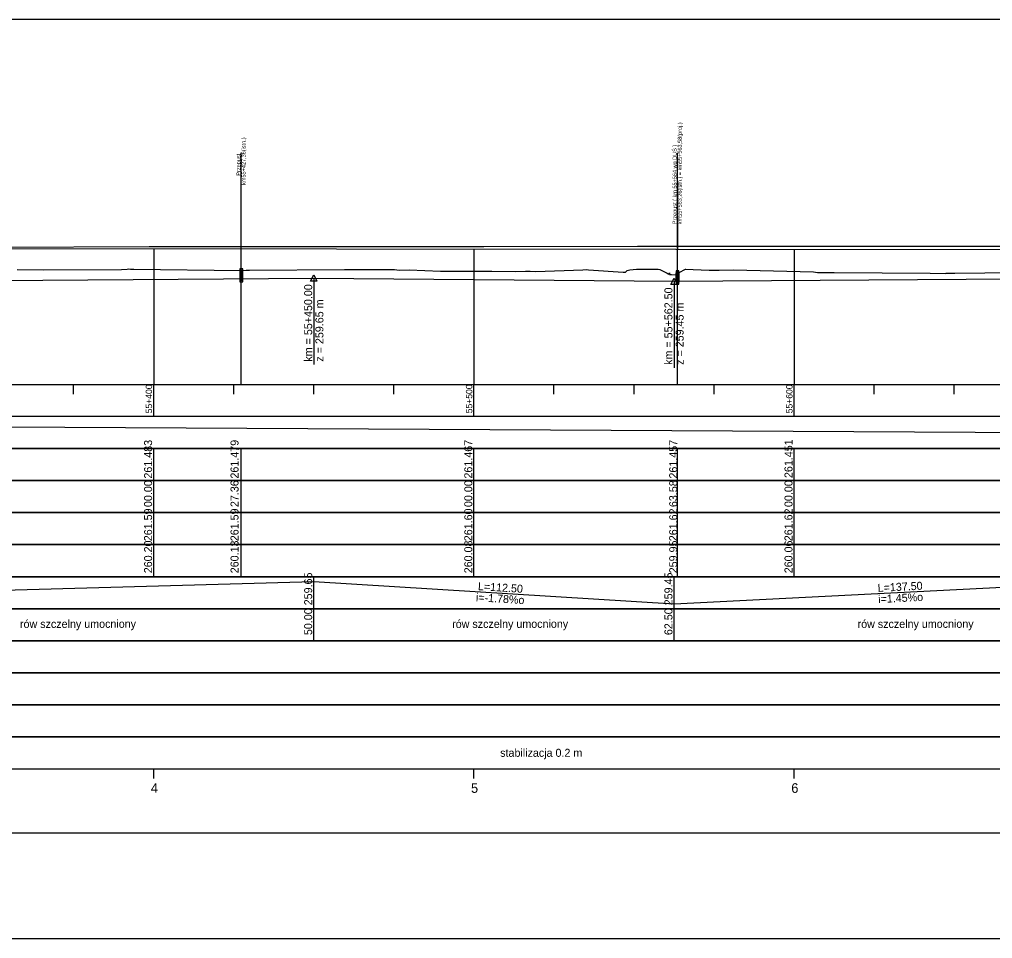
# Model space of a CAD drawing. Extents: x 6445630 to 6518227, y 5499240 to 5511716.
# Drawn here: x 6454589.3 to 6454893.2, y 5508418.3 to 5508705.3 of the extents above; entities that cross this region are included whole.
import ezdxf

# ---------------------------------------------------------------- set-up
doc = ezdxf.new("R2010")
doc.units = 0
for name, color, linetype in [('TOR_PROF-obiekty+opisy', 7, 'Continuous'), ('TOR_PROF-opisy pomocnicze', 7, 'Continuous'), ('TOR_PROF-rowy otwarte', 7, 'Continuous'), ('TOR_PROF-tabelka-geometria T1', 7, 'Continuous'), ('TOR_PROF-tabelka-kilometracja', 7, 'Continuous'), ('TOR_PROF-tabelka-odleglosci T1', 7, 'Continuous'), ('TOR_PROF-tabelka-pochylenia proj T1', 7, 'Continuous'), ('TOR_PROF-tabelka-rodzaj rowu T1', 7, 'Continuous'), ('TOR_PROF-tabelka-rowyT1', 7, 'Continuous'), ('TOR_PROF-tabelka-rurociagi T1', 7, 'Continuous'), ('TOR_PROF-tabelka-rzedne istn T1', 7, 'Continuous'), ('TOR_PROF-tabelka-rzedne proj T1', 7, 'Continuous'), ('TOR_PROF-tabelka-teren istniejacy T1', 7, 'Continuous'), ('TOR_PROF-tabelka-warstwa ochronna T1', 7, 'Continuous'), ('TOR_PROF-tor istniejacy T2', 7, 'Continuous'), ('TOR_PROF-tor projektowany', 7, 'Continuous'), ('TOR_PROF-uklad odniesienia', 7, 'Continuous'), ('TOR_PROF-warstwa ochronna', 7, 'Continuous'), ('TOR_RAMKI-dodatkowe3', 7, 'Continuous'), ('TOR_RAMKI-MASKA WYCIECIA', 7, 'Continuous')]:
    doc.layers.add(name, color=color, linetype=linetype)

msp = doc.modelspace()

# ---------------------------------------------------------------- linework, layer by layer
at = {"layer": 'TOR_PROF-obiekty+opisy'}
for p, q in [((6454658.57, 5508591.29), (6454658.57, 5508663.68)), ((6454794.79, 5508591.29), (6454794.79, 5508663.58)), ((6454794.79, 5508654.58), (6454794.79, 5508633.58)), ((6454794.79, 5508654.58), (6454794.79, 5508633.58))]:
    msp.add_line(p, q, dxfattribs=at)
for points in [[(6454659.03, 5508627.39), (6454658.11, 5508627.39), (6454658.11, 5508623.31), (6454659.03, 5508623.31)], [(6454658.95, 5508626.85), (6454658.2, 5508626.85), (6454658.2, 5508623.85), (6454658.95, 5508623.85)], [(6454795.25, 5508626.76), (6454794.33, 5508626.76), (6454794.33, 5508622.68), (6454795.25, 5508622.68)], [(6454795.17, 5508626.22), (6454794.42, 5508626.22), (6454794.42, 5508623.22), (6454795.17, 5508623.22)]]:
    msp.add_lwpolyline(points, close=True, dxfattribs=at)
for points in [[(6454659.03, 5508623.31), (6454659.03, 5508627.39), (6454658.11, 5508627.39), (6454658.11, 5508623.31), (6454659.03, 5508623.31)], [(6454658.95, 5508623.85), (6454658.2, 5508623.85), (6454658.2, 5508626.85), (6454658.95, 5508626.85), (6454658.95, 5508623.85)], [(6454795.25, 5508622.68), (6454795.25, 5508626.76), (6454794.33, 5508626.76), (6454794.33, 5508622.68), (6454795.25, 5508622.68)], [(6454795.17, 5508623.22), (6454794.42, 5508623.22), (6454794.42, 5508626.22), (6454795.17, 5508626.22), (6454795.17, 5508623.22)]]:
    msp.add_lwpolyline(points, dxfattribs=at)
at = {"layer": 'TOR_PROF-opisy pomocnicze'}
for p, q in [((6454681.21, 5508624.54), (6454681.21, 5508597.54)), ((6454793.71, 5508623.54), (6454793.71, 5508596.54))]:
    msp.add_line(p, q, dxfattribs=at)
for points in [[(6454681.21, 5508625.54), (6454682.21, 5508623.54), (6454680.21, 5508623.54)], [(6454793.71, 5508624.54), (6454794.71, 5508622.54), (6454792.71, 5508622.54)]]:
    msp.add_lwpolyline(points, close=True, dxfattribs=at)
at = {"layer": 'TOR_PROF-rowy otwarte'}
for p, q in [((6454431.21, 5508622.54), (6454681.21, 5508624.54)), ((6454681.21, 5508624.54), (6454793.71, 5508623.54)), ((6454793.71, 5508623.54), (6454931.21, 5508624.54))]:
    msp.add_line(p, q, dxfattribs=at)
at = {"layer": 'TOR_PROF-tabelka-geometria T1'}
for points in [[(6452331.21, 5508451.29), (6453331.21, 5508451.29), (6453331.21, 5508448.62), (6453416.22, 5508448.62), (6453416.22, 5508451.29), (6453496.22, 5508451.29), (6453496.22, 5508453.96), (6453581.21, 5508453.96), (6453581.21, 5508451.29), (6457347.56, 5508451.29), (6457347.56, 5508448.62), (6457429.11, 5508448.62), (6457429.11, 5508451.29), (6457509.11, 5508451.29), (6457509.11, 5508453.96), (6457590.67, 5508453.96), (6457590.67, 5508451.29), (6459780.93, 5508451.29)], [(6452331.21, 5508451.29), (6462731.21, 5508451.29)]]:
    msp.add_lwpolyline(points, dxfattribs=at)
at = {"layer": 'TOR_PROF-tabelka-kilometracja'}
for points in [[(6454631.21, 5508468.29), (6454631.21, 5508471.29)], [(6454731.21, 5508468.29), (6454731.21, 5508471.29)], [(6454831.21, 5508468.29), (6454831.21, 5508471.29)]]:
    msp.add_lwpolyline(points, dxfattribs=at)
at = {"layer": 'TOR_PROF-tabelka-odleglosci T1'}
msp.add_lwpolyline([(6452331.21, 5508551.29), (6462731.21, 5508551.29), (6462731.21, 5508561.29), (6452331.21, 5508561.29)], close=True, dxfattribs=at)
for points in [[(6454631.21, 5508551.29), (6454631.21, 5508561.29)], [(6454658.57, 5508551.29), (6454658.57, 5508561.29)], [(6454731.21, 5508551.29), (6454731.21, 5508561.29)], [(6454794.79, 5508551.29), (6454794.79, 5508561.29)], [(6454831.21, 5508551.29), (6454831.21, 5508561.29)]]:
    msp.add_lwpolyline(points, dxfattribs=at)
at = {"layer": 'TOR_PROF-tabelka-pochylenia proj T1'}
msp.add_lwpolyline([(6452331.21, 5508571.29), (6462731.21, 5508571.29), (6462731.21, 5508581.29), (6452331.21, 5508581.29)], close=True, dxfattribs=at)
msp.add_lwpolyline([(6454281.21, 5508579.79), (6455551.21, 5508572.79)], dxfattribs=at)
at = {"layer": 'TOR_PROF-tabelka-rodzaj rowu T1'}
for points in [[(6452331.21, 5508511.29), (6462731.21, 5508511.29), (6462731.21, 5508521.29), (6452331.21, 5508521.29)], [(6452331.21, 5508511.29), (6462731.21, 5508511.29), (6462731.21, 5508521.29), (6452331.21, 5508521.29)], [(6452331.21, 5508491.29), (6462731.21, 5508491.29), (6462731.21, 5508501.29), (6452331.21, 5508501.29)]]:
    msp.add_lwpolyline(points, close=True, dxfattribs=at)
for points in [[(6454681.21, 5508511.29), (6454681.21, 5508521.29)], [(6454793.71, 5508511.29), (6454793.71, 5508521.29)]]:
    msp.add_lwpolyline(points, dxfattribs=at)
at = {"layer": 'TOR_PROF-tabelka-rowyT1'}
msp.add_lwpolyline([(6452331.21, 5508521.29), (6462731.21, 5508521.29), (6462731.21, 5508531.29), (6452331.21, 5508531.29)], close=True, dxfattribs=at)
msp.add_lwpolyline([(6452331.21, 5508521.29), (6462731.21, 5508521.29), (6462731.21, 5508531.29), (6452331.21, 5508531.29)], close=True, dxfattribs=at)
msp.add_lwpolyline([(6452331.21, 5508521.29), (6462731.21, 5508521.29), (6462731.21, 5508531.29), (6452331.21, 5508531.29)], close=True, dxfattribs=at)
for points in [[(6454431.21, 5508522.79), (6454681.21, 5508529.79)], [(6454681.21, 5508521.29), (6454681.21, 5508531.29)], [(6454681.21, 5508529.79), (6454793.71, 5508522.79)], [(6454793.71, 5508521.29), (6454793.71, 5508531.29)], [(6454793.71, 5508522.79), (6454931.21, 5508529.79)]]:
    msp.add_lwpolyline(points, dxfattribs=at)
at = {"layer": 'TOR_PROF-tabelka-rurociagi T1'}
msp.add_lwpolyline([(6452331.21, 5508501.29), (6462731.21, 5508501.29), (6462731.21, 5508511.29), (6452331.21, 5508511.29)], close=True, dxfattribs=at)
at = {"layer": 'TOR_PROF-tabelka-rzedne istn T1'}
msp.add_lwpolyline([(6452331.21, 5508541.29), (6462731.21, 5508541.29), (6462731.21, 5508551.29), (6452331.21, 5508551.29)], close=True, dxfattribs=at)
for points in [[(6454631.21, 5508541.29), (6454631.21, 5508551.29)], [(6454658.57, 5508541.29), (6454658.57, 5508551.29)], [(6454731.21, 5508541.29), (6454731.21, 5508551.29)], [(6454794.79, 5508541.29), (6454794.79, 5508551.29)], [(6454831.21, 5508541.29), (6454831.21, 5508551.29)], [(6454631.21, 5508531.29), (6454631.21, 5508541.29)], [(6454631.21, 5508531.29), (6454631.21, 5508541.29)], [(6454631.21, 5508531.29), (6454631.21, 5508541.29)], [(6454631.21, 5508531.29), (6454631.21, 5508541.29)], [(6454658.57, 5508531.29), (6454658.57, 5508541.29)], [(6454731.21, 5508531.29), (6454731.21, 5508541.29)], [(6454731.21, 5508531.29), (6454731.21, 5508541.29)], [(6454731.21, 5508531.29), (6454731.21, 5508541.29)], [(6454731.21, 5508531.29), (6454731.21, 5508541.29)], [(6454794.79, 5508531.29), (6454794.79, 5508541.29)], [(6454831.21, 5508531.29), (6454831.21, 5508541.29)], [(6454831.21, 5508531.29), (6454831.21, 5508541.29)], [(6454831.21, 5508531.29), (6454831.21, 5508541.29)], [(6454831.21, 5508531.29), (6454831.21, 5508541.29)]]:
    msp.add_lwpolyline(points, dxfattribs=at)
at = {"layer": 'TOR_PROF-tabelka-rzedne proj T1'}
msp.add_lwpolyline([(6452331.21, 5508561.29), (6462731.21, 5508561.29), (6462731.21, 5508571.29), (6452331.21, 5508571.29)], close=True, dxfattribs=at)
for points in [[(6454631.21, 5508561.29), (6454631.21, 5508571.29)], [(6454658.57, 5508561.29), (6454658.57, 5508571.29)], [(6454731.21, 5508561.29), (6454731.21, 5508571.29)], [(6454794.79, 5508561.29), (6454794.79, 5508571.29)], [(6454831.21, 5508561.29), (6454831.21, 5508571.29)]]:
    msp.add_lwpolyline(points, dxfattribs=at)
at = {"layer": 'TOR_PROF-tabelka-teren istniejacy T1'}
msp.add_lwpolyline([(6452331.21, 5508531.29), (6462731.21, 5508531.29), (6462731.21, 5508541.29), (6452331.21, 5508541.29)], close=True, dxfattribs=at)
msp.add_lwpolyline([(6452331.21, 5508531.29), (6462731.21, 5508531.29), (6462731.21, 5508541.29), (6452331.21, 5508541.29)], close=True, dxfattribs=at)
msp.add_lwpolyline([(6452331.21, 5508531.29), (6462731.21, 5508531.29), (6462731.21, 5508541.29), (6452331.21, 5508541.29)], close=True, dxfattribs=at)
msp.add_lwpolyline([(6452331.21, 5508531.29), (6462731.21, 5508531.29), (6462731.21, 5508541.29), (6452331.21, 5508541.29)], close=True, dxfattribs=at)
at = {"layer": 'TOR_PROF-tabelka-warstwa ochronna T1'}
msp.add_lwpolyline([(6452331.21, 5508481.29), (6462731.21, 5508481.29), (6462731.21, 5508491.29), (6452331.21, 5508491.29)], close=True, dxfattribs=at)
at = {"layer": 'TOR_PROF-tor istniejacy T2'}
msp.add_lwpolyline([(6455230.6, 5508634.64), (6455180.37, 5508634.54), (6455131.29, 5508634.54), (6455081.1, 5508634.59), (6455031.43, 5508634.54), (6454982.33, 5508634.44), (6454932.17, 5508634.44), (6454881.46, 5508634.44), (6454831.03, 5508634.39), (6454782.28, 5508634.39), (6454734.31, 5508634.29), (6454682.33, 5508634.24), (6454629.77, 5508634.24), (6454582.54, 5508634.09)], dxfattribs=at)
at = {"layer": 'TOR_PROF-tor projektowany'}
msp.add_line((6454281.21, 5508633.98), (6455551.21, 5508632.98), dxfattribs=at)
msp.add_line((6454281.21, 5508633.98), (6455551.21, 5508632.98), dxfattribs=at)
for points in [[(6454631.21, 5508633.7), (6454631.21, 5508596.29), (6454631.21, 5508591.29), (6454631.21, 5508591.29)], [(6454631.21, 5508633.7), (6454631.21, 5508596.29), (6454631.21, 5508591.29), (6454631.21, 5508591.29)], [(6454731.21, 5508633.63), (6454731.21, 5508596.29), (6454731.21, 5508591.29), (6454731.21, 5508591.29)], [(6454731.21, 5508633.63), (6454731.21, 5508596.29), (6454731.21, 5508591.29), (6454731.21, 5508591.29)], [(6454831.21, 5508633.55), (6454831.21, 5508596.29), (6454831.21, 5508591.29), (6454831.21, 5508591.29)], [(6454831.21, 5508633.55), (6454831.21, 5508596.29), (6454831.21, 5508591.29), (6454831.21, 5508591.29)]]:
    msp.add_lwpolyline(points, dxfattribs=at)
at = {"layer": 'TOR_PROF-uklad odniesienia'}
for p, q in [((6452331.21, 5508591.29), (6462731.21, 5508591.29)), ((6452331.21, 5508591.29), (6462731.21, 5508591.29)), ((6454606.21, 5508588.29), (6454606.21, 5508591.29)), ((6454606.21, 5508588.29), (6454606.21, 5508591.29)), ((6454631.21, 5508581.29), (6454631.21, 5508591.29)), ((6454631.21, 5508581.29), (6454631.21, 5508591.29)), ((6454656.21, 5508588.29), (6454656.21, 5508591.29)), ((6454656.21, 5508588.29), (6454656.21, 5508591.29)), ((6454681.21, 5508588.29), (6454681.21, 5508591.29)), ((6454681.21, 5508588.29), (6454681.21, 5508591.29)), ((6454706.21, 5508588.29), (6454706.21, 5508591.29)), ((6454706.21, 5508588.29), (6454706.21, 5508591.29)), ((6454731.21, 5508581.29), (6454731.21, 5508591.29)), ((6454731.21, 5508581.29), (6454731.21, 5508591.29)), ((6454756.21, 5508588.29), (6454756.21, 5508591.29)), ((6454756.21, 5508588.29), (6454756.21, 5508591.29)), ((6454781.21, 5508588.29), (6454781.21, 5508591.29)), ((6454781.21, 5508588.29), (6454781.21, 5508591.29)), ((6454806.21, 5508588.29), (6454806.21, 5508591.29)), ((6454806.21, 5508588.29), (6454806.21, 5508591.29)), ((6454831.21, 5508581.29), (6454831.21, 5508591.29)), ((6454831.21, 5508581.29), (6454831.21, 5508591.29)), ((6454856.21, 5508588.29), (6454856.21, 5508591.29)), ((6454856.21, 5508588.29), (6454856.21, 5508591.29)), ((6454881.21, 5508588.29), (6454881.21, 5508591.29)), ((6454881.21, 5508588.29), (6454881.21, 5508591.29))]:
    msp.add_line(p, q, dxfattribs=at)
at = {"layer": 'TOR_PROF-warstwa ochronna'}
msp.add_lwpolyline([(6452331.21, 5508471.29), (6462731.21, 5508471.29), (6462731.21, 5508481.29), (6452331.21, 5508481.29)], close=True, dxfattribs=at)
at = {"layer": 'TOR_RAMKI-dodatkowe3'}
for p, q in [((6454588.59, 5508627.19), (6454596.77, 5508627.12)), ((6454596.77, 5508627.12), (6454621.18, 5508627.25)), ((6454621.18, 5508627.25), (6454622.96, 5508627.36)), ((6454622.96, 5508627.36), (6454623.36, 5508627.37)), ((6454623.36, 5508627.37), (6454623.98, 5508627.36)), ((6454623.98, 5508627.36), (6454625.02, 5508627.36)), ((6454625.02, 5508627.36), (6454658.46, 5508626.93)), ((6454658.46, 5508626.93), (6454658.83, 5508626.92)), ((6454658.83, 5508626.92), (6454660.1, 5508626.99)), ((6454660.1, 5508626.99), (6454661.16, 5508627)), ((6454661.16, 5508627), (6454690.78, 5508627.25)), ((6454690.78, 5508627.25), (6454706.38, 5508627.16)), ((6454706.38, 5508627.16), (6454707.9, 5508627.01)), ((6454707.9, 5508627.01), (6454710.99, 5508627.07)), ((6454710.99, 5508627.07), (6454720.78, 5508626.69)), ((6454720.78, 5508626.69), (6454736.83, 5508626.67)), ((6454736.83, 5508626.67), (6454744.1, 5508626.6)), ((6454744.1, 5508626.6), (6454747.36, 5508626.66)), ((6454747.36, 5508626.66), (6454748.74, 5508626.66)), ((6454748.74, 5508626.66), (6454750.59, 5508626.61)), ((6454750.59, 5508626.61), (6454765.24, 5508627.1)), ((6454765.24, 5508627.1), (6454766.31, 5508627.17)), ((6454766.31, 5508627.17), (6454766.98, 5508627.12)), ((6454766.98, 5508627.12), (6454777.78, 5508626.42)), ((6454777.78, 5508626.42), (6454778.35, 5508626.36)), ((6454778.35, 5508626.36), (6454778.54, 5508626.36)), ((6454778.54, 5508626.36), (6454779.06, 5508626.87)), ((6454779.06, 5508626.87), (6454779.91, 5508627.06)), ((6454779.91, 5508627.06), (6454781.95, 5508627.3)), ((6454781.95, 5508627.3), (6454788.8, 5508627.3)), ((6454788.8, 5508627.3), (6454789.28, 5508627.26)), ((6454789.28, 5508627.26), (6454791.59, 5508626.09)), ((6454791.59, 5508626.09), (6454792.06, 5508625.76)), ((6454792.06, 5508625.76), (6454792.28, 5508626.18)), ((6454792.28, 5508626.18), (6454792.41, 5508625.53)), ((6454792.41, 5508625.53), (6454792.7, 5508625.62)), ((6454792.7, 5508625.62), (6454792.96, 5508625.68)), ((6454792.96, 5508625.68), (6454794.3, 5508625.59)), ((6454794.3, 5508625.59), (6454794.63, 5508625.71)), ((6454794.63, 5508625.71), (6454794.71, 5508626.03)), ((6454794.71, 5508626.03), (6454795.35, 5508626.3)), ((6454795.35, 5508626.3), (6454797.32, 5508627.33)), ((6454797.32, 5508627.33), (6454797.39, 5508627.33)), ((6454797.39, 5508627.33), (6454799.66, 5508627.22)), ((6454799.66, 5508627.22), (6454804.72, 5508627.01)), ((6454804.72, 5508627.01), (6454805.85, 5508626.96)), ((6454805.85, 5508626.96), (6454807.84, 5508627.05)), ((6454807.84, 5508627.05), (6454812.28, 5508627.11)), ((6454812.28, 5508627.11), (6454837.29, 5508626.43)), ((6454837.29, 5508626.43), (6454838.5, 5508626.28)), ((6454838.5, 5508626.28), (6454838.82, 5508626.24)), ((6454838.82, 5508626.24), (6454839.25, 5508626.3)), ((6454839.25, 5508626.3), (6454839.87, 5508626.32)), ((6454839.87, 5508626.32), (6454843.75, 5508626.27)), ((6454843.75, 5508626.27), (6454873.75, 5508626.04)), ((6454873.75, 5508626.04), (6454878.42, 5508626.01)), ((6454878.42, 5508626.01), (6454878.65, 5508626.02)), ((6454878.65, 5508626.02), (6454879.16, 5508626.05)), ((6454879.16, 5508626.05), (6454881.39, 5508626.08)), ((6454881.39, 5508626.08), (6454905.33, 5508626.31))]:
    msp.add_line(p, q, dxfattribs=at)
at = {"layer": 'TOR_RAMKI-MASKA WYCIECIA'}
msp.add_lwpolyline([(6454268.59, 5508418.29), (6456268.59, 5508418.29), (6456268.59, 5508705.29), (6454268.59, 5508705.29)], close=True, dxfattribs=at)

# ---------------------------------------------------------------- texts
at = {"layer": 'TOR_PROF-obiekty+opisy'}
for s, p in [(' km55+563,26(istn.) = km55+563,58(proj.) ', (6454796.14, 5508640.88)), (' km55+427,36(istn.) ', (6454659.91, 5508653.15)), (' Przepust ( km 55+564 wg DUŚ )', (6454794.53, 5508640.88)), ('       Przepust', (6454658.29, 5508653.15))]:
    msp.add_text(s, height=1.25, rotation=90, dxfattribs=at).set_placement(p)
at = {"layer": 'TOR_PROF-opisy pomocnicze'}
for s, p in [('km = 55+450.00', (6454680.71, 5508598.44)), ('km = 55+562.50', (6454793.21, 5508597.44)), ('z = 259.65 m', (6454684.21, 5508598.44)), ('z = 259.45 m', (6454796.71, 5508597.44))]:
    msp.add_text(s, height=2.5, rotation=90, dxfattribs=at).set_placement(p)
at = {"layer": 'TOR_PROF-tabelka-kilometracja'}
for s, p in [('4', (6454630.32, 5508463.79)), ('5', (6454730.31, 5508463.79)), ('6', (6454830.32, 5508463.79))]:
    msp.add_text(s, height=3, dxfattribs=at).set_placement(p)
at = {"layer": 'TOR_PROF-tabelka-odleglosci T1'}
for s, p in [('00.00', (6454630.71, 5508553.03)), ('27.36', (6454657.71, 5508553.02)), ('00.00', (6454730.71, 5508553.03)), ('63.58', (6454794.71, 5508553.02)), ('00.00', (6454830.71, 5508553.03))]:
    msp.add_text(s, height=2.5, rotation=90, dxfattribs=at).set_placement(p)
at = {"layer": 'TOR_PROF-tabelka-rodzaj rowu T1'}
for s, p in [('50.00', (6454680.71, 5508513.04)), ('62.50', (6454793.21, 5508513.04))]:
    msp.add_text(s, height=2.5, rotation=90, dxfattribs=at).set_placement(p)
at = {"layer": 'TOR_PROF-tabelka-rowyT1'}
for s, rotation, p in [('259.65', 90, (6454680.71, 5508522.35)), ('259.45', 90, (6454793.21, 5508522.35)), ('L=112.50', 356.4395, (6454732.43, 5508527.1)), ('L=137.50', 2.9144, (6454857.37, 5508526.53)), ('i=-1.78%o', 356.4395, (6454731.79, 5508523.64)), ('i=1.45%o', 2.9144, (6454857.53, 5508523.03)), ('rów szczelny umocniony', 0.087, (6454589.46, 5508515.27)), ('rów szczelny umocniony', 0.087, (6454724.42, 5508515.27)), ('rów szczelny umocniony', 0.087, (6454851.04, 5508515.27))]:
    msp.add_text(s, height=2.5, rotation=rotation, dxfattribs=at).set_placement(p)
at = {"layer": 'TOR_PROF-tabelka-rzedne istn T1'}
for s, p in [('261.59', (6454630.71, 5508542.36)), ('261.59', (6454657.71, 5508542.36)), ('261.60', (6454730.71, 5508542.36)), ('261.62', (6454794.71, 5508542.36)), ('261.62', (6454830.71, 5508542.36)), ('260.20', (6454630.71, 5508532.36)), ('260.13', (6454657.71, 5508532.35)), ('260.08', (6454730.71, 5508532.35)), ('259.95', (6454794.71, 5508532.35)), ('260.06', (6454830.71, 5508532.35))]:
    msp.add_text(s, height=2.5, rotation=90, dxfattribs=at).set_placement(p)
at = {"layer": 'TOR_PROF-tabelka-rzedne proj T1'}
for s, p in [('261.451', (6454830.71, 5508562.09)), ('261.483', (6454630.71, 5508561.92)), ('261.479', (6454657.71, 5508561.93)), ('261.467', (6454730.71, 5508561.93)), ('261.457', (6454794.71, 5508561.93))]:
    msp.add_text(s, height=2.5, rotation=90, dxfattribs=at).set_placement(p)
at = {"layer": 'TOR_PROF-uklad odniesienia'}
for s, p in [('55+400', (6454630.71, 5508582.31)), ('55+400', (6454630.71, 5508582.31)), ('55+500', (6454730.71, 5508582.31)), ('55+500', (6454730.71, 5508582.31)), ('55+600', (6454830.71, 5508582.31)), ('55+600', (6454830.71, 5508582.31))]:
    msp.add_text(s, height=2, rotation=90, dxfattribs=at).set_placement(p)
at = {"layer": 'TOR_PROF-warstwa ochronna'}
msp.add_text('stabilizacja 0.2 m', height=2.5, rotation=360, dxfattribs=at).set_placement((6454739.42, 5508475.04))

doc.saveas('drawing.dxf')
